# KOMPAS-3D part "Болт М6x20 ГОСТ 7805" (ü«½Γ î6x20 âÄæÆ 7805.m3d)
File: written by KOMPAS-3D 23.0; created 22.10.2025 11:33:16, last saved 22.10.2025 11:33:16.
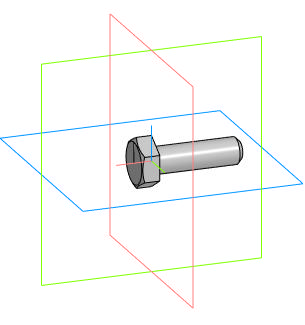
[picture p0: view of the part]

Document properties: Автор: ARM_513_VVK; Полное имя файла: F:\Демо\Демо вариант космос\Болт М6x20 ГОСТ 7805.m3d

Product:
- Part/product: Болт М6x20 ГОСТ 7805

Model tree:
1. Операция без истории:1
